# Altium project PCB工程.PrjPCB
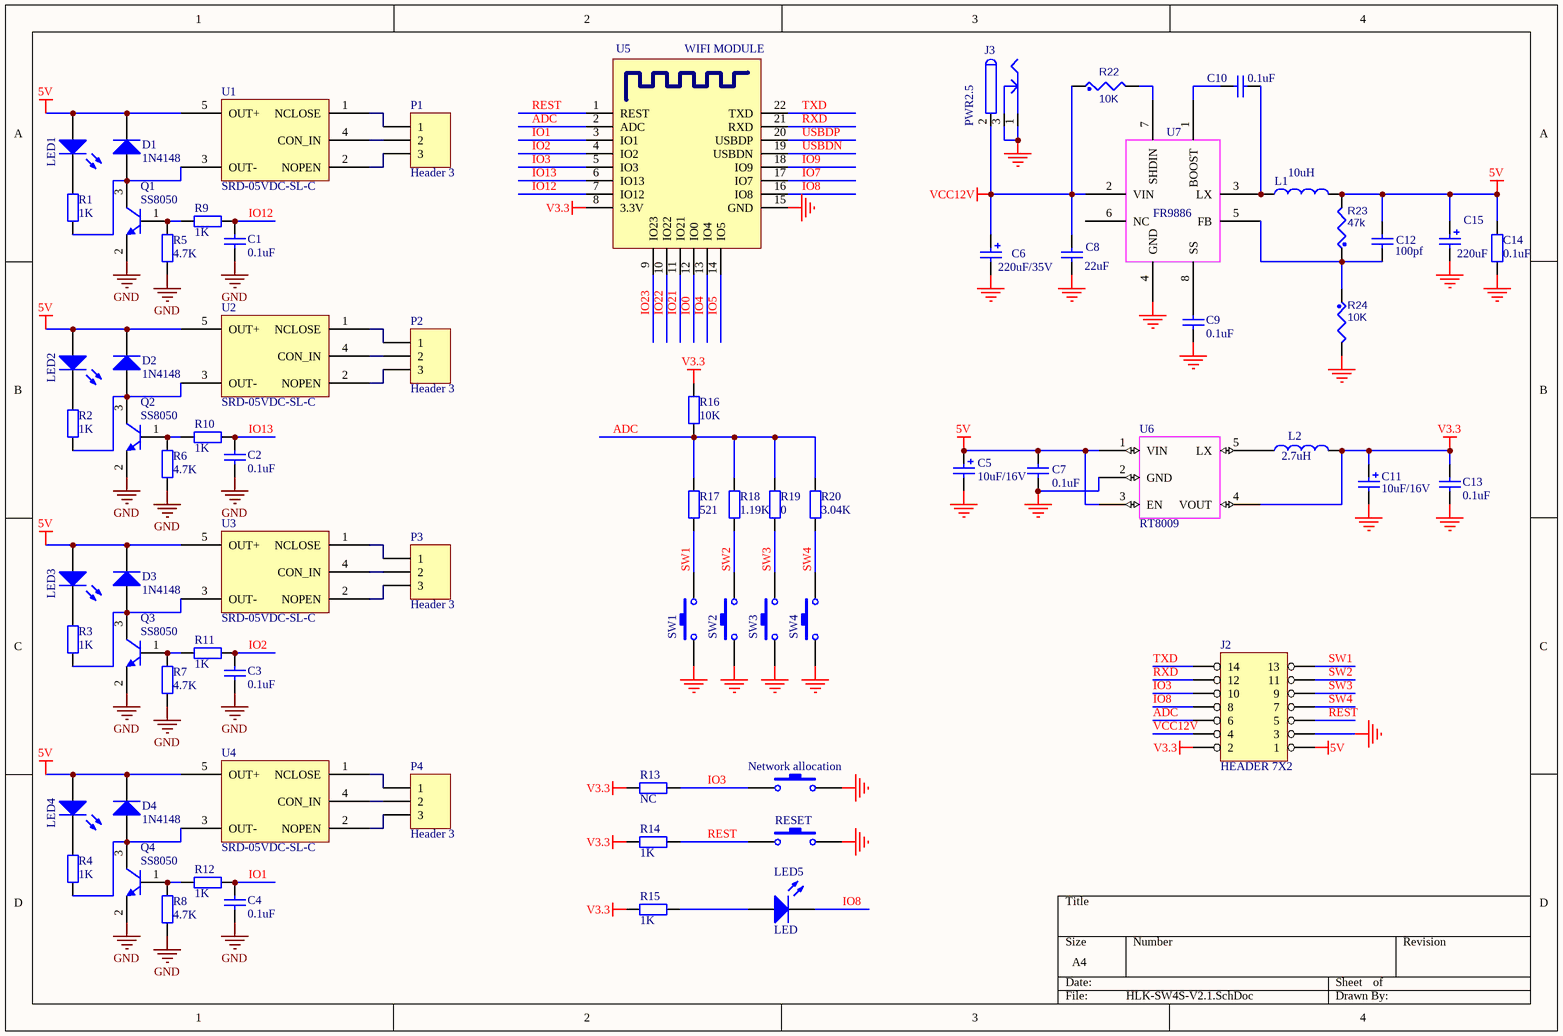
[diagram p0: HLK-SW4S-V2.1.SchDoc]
1 sheet, 72 parts. Net scope: global (net labels, ports and power ports of the same name join across sheets).
Board file: HLK-SW4S-V2.1.PcbDoc

## Sheet HLK-SW4S-V2.1.SchDoc
size A4

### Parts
C1  0.1uF  [0603L]
C2  0.1uF  [0603L]
C3  0.1uF  [0603L]
C4  0.1uF  [0603L]
C5  10uF/16V  [0805S]
C6  220uF/35V  [CAP_SMT_6.3]
C7  0.1uF  [0603L]
C8  22uF  [0805S]
C9  0.1uF  [0603L]
C10  0.1uF  [0603L]
C11  10uF/16V  [0805S]
C12  100pf  [0603L]
C13  0.1uF  [0603L]
C14  0.1uF  [0805S]
C15  220uF  [CAP_SMT_6.3]
D1  1N4148  [LED1]
D2  1N4148  [LED1]
D3  1N4148  [LED1]
D4  1N4148  [LED1]
J2  HEADER 7X2  [HDR2X7]
J3  PWR2.5  [POWER_STK1]
L1  10uH  [L7x7]
L2  2.7uH  [L322520]
LED1  LED  [0603LED]  (value not drawn)
LED2  LED  [0603LED]  (value not drawn)
LED3  LED  [0603LED]  (value not drawn)
LED4  LED  [0603LED]  (value not drawn)
LED5  LED  [0603LED]
Network_allocation  SW-PB  [KEY]  (value not drawn)
P1  Header 3  [5MMX3]
P2  Header 3  [5MMX3]
P3  Header 3  [5MMX3]
P4  Header 3  [5MMX3]
Q1  SS8050  [SOT-23]
Q2  SS8050  [SOT-23]
Q3  SS8050  [SOT-23]
Q4  SS8050  [SOT-23]
R1  1K  [0603L]
R2  1K  [0603L]
R3  1K  [0603L]
R4  1K  [0603L]
R5  4.7K  [0603L]
R6  4.7K  [0603L]
R7  4.7K  [0603L]
R8  4.7K  [0603L]
R9  1K  [0603L]
R10  1K  [0603L]
R11  1K  [0603L]
R12  1K  [0603L]
R13  NC  [0603L]
R14  1K  [0603L]
R15  1K  [0603L]
R16  10K  [0603L]
R17  521  [0603L]
R18  1.19K  [0603L]
R19  0  [0603L]
R20  3.04K  [0603L]
R22  10K  [0603L]
R23  47k  [0603L]
R24  10K  [0603L]
RESET  SW-PB  [KEY]  (value not drawn)
SW1  SW-PB  [KEY]  (value not drawn)
SW2  SW-PB  [KEY]  (value not drawn)
SW3  SW-PB  [KEY]  (value not drawn)
SW4  SW-PB  [KEY]  (value not drawn)
U1  SRD-05VDC-SL-C  [SRD-05VDC-SL-C]
U2  SRD-05VDC-SL-C  [SRD-05VDC-SL-C]
U3  SRD-05VDC-SL-C  [SRD-05VDC-SL-C]
U4  SRD-05VDC-SL-C  [SRD-05VDC-SL-C]
U5  WIFI MODULE  [MOD1]
U6  RT8009  [SOT-25]
U7  FR9886  [SOP8]

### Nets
5V: C5.1 C7.2 C12.1 C14.2 C15.1 D1.2(K) D2.2(K) D3.2(K) D4.2(K) J2.1 L1.2 LED1.1(A) LED2.1(A) LED3.1(A) LED4.1(A) R23.2 U1.5(OUT+) U2.5(OUT+) U3.5(OUT+) U4.5(OUT+) U6.1(VIN) U6.3(EN)
GND: C1.1 C2.1 C3.1 C4.1 C5.2 C6.2 C7.1 C8.2 C9.1 C11.2 C13.1 C14.1 C15.2 J2.3 J3.1 J3.3 Network_allocation.2 Q1.2(E) Q2.2(E) Q3.2(E) Q4.2(E) R5.1 R6.1 R7.1 R8.1 R24.2 RESET.1 SW1.1 SW2.1 SW3.1 SW4.1 U5.15(GND) U6.2(GND) U7.4(GND)
V3.3: C11.1 C13.2 J2.2 L2.2 R13.1 R14.1 R15.2 R16.2 U5.8(3.3V) U6.4(VOUT)
VCC12V: C6.1 C8.1 J2.4 J3.2 R22.1 U7.2(VIN)
ADC: J2.6 R16.1 R17.2 R18.2 R19.2 R20.2 U5.2(ADC)
IO0: U5.12(IO0)
IO1: C4.2 R12.2 U5.3(IO1)
IO2: C3.2 R11.2 U5.4(IO2)
IO3: J2.10 Network_allocation.1 R13.2 U5.5(IO3)
IO4: U5.13(IO4)
IO5: U5.14(IO5)
IO7: U5.17(IO7)
IO8: J2.8 LED5.2(K) U5.16(IO8)
IO9: U5.18(IO9)
IO12: C1.2 R9.2 U5.7(IO12)
IO13: C2.2 R10.1 U5.6(IO13)
IO21: U5.11(IO21)
IO22: U5.10(IO22)
IO23: U5.9(IO23)
REST: J2.5 R14.2 RESET.2 U5.1(REST)
RXD: J2.12 U5.21(RXD)
SW1: J2.13 R17.1 SW1.2
SW2: J2.11 R18.1 SW2.2
SW3: J2.9 R19.1 SW3.2
SW4: J2.7 R20.1 SW4.2
TXD: J2.14 U5.22(TXD)
USBDN: U5.19(USBDN)
USBDP: U5.20(USBDP)
NetC9_2: C9.2 U7.8(SS)
NetC10_1: C10.1 L1.1 U7.3(LX)
NetC10_2: C10.2 U7.1(BOOST)
NetC12_2: C12.2 R23.1 R24.1 U7.5(FB)
NetD1_1: D1.1(A) Q1.3(C) R1.1 U1.3(OUT-)
NetD2_1: D2.1(A) Q2.3(C) R2.1 U2.3(OUT-)
NetD3_1: D3.1(A) Q3.3(C) R3.1 U3.3(OUT-)
NetD4_1: D4.1(A) Q4.3(C) R4.1 U4.3(OUT-)
NetL2_1: L2.1 U6.5(LX)
NetLED1_2: LED1.2(K) R1.2
NetLED2_2: LED2.2(K) R2.2
NetLED3_2: LED3.2(K) R3.2
NetLED4_2: LED4.2(K) R4.2
NetLED5_1: LED5.1(A) R15.1
NetP1_1: P1.1 U1.1(NCLOSE)
NetP1_2: P1.2 U1.4(CON_IN)
NetP1_3: P1.3 U1.2(NOPEN)
NetP2_1: P2.1 U2.1(NCLOSE)
NetP2_2: P2.2 U2.4(CON_IN)
NetP2_3: P2.3 U2.2(NOPEN)
NetP3_1: P3.1 U3.1(NCLOSE)
NetP3_2: P3.2 U3.4(CON_IN)
NetP3_3: P3.3 U3.2(NOPEN)
NetP4_1: P4.1 U4.1(NCLOSE)
NetP4_2: P4.2 U4.4(CON_IN)
NetP4_3: P4.3 U4.2(NOPEN)
NetQ1_1: Q1.1(B) R5.2 R9.1
NetQ2_1: Q2.1(B) R6.2 R10.2
NetQ3_1: Q3.1(B) R7.2 R11.1
NetQ4_1: Q4.1(B) R8.2 R12.1
NetR22_2: R22.2 U7.7(SHDIN)

Not connected (* = marked no-connect by the designer): U7 6(NC)

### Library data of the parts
C1-C4 C7-C10 C13 = Cap: Capacitor; Manufacturer: Generic Components; Class: Passive; Value: 100pF
C5 C6 C11 C15 = Cap Pol3: Polarized Capacitor (Surface Mount); Manufacturer: Generic Components; Class: Passive; Value: 10uF
C12 = Cap: Capacitor; Manufacturer: Generic Components; Class: Passive
C14 R1-R15 R17-R20 = Res2: Resistor; Value: 10K
D1-D4 = Diode: Default Diode
J3 = PWR2.5: Low Voltage Power Supply Connector
L1 L2 = INDUCTOR1
LED1-LED5 = LED0: Typical INFRARED GaAs LED
Network_allocation RESET SW1-SW4 = SW-PB: Switch
P1-P4 = Header 3: Header, 3-Pin
Q1-Q4 = 2N3904: PNP General Purpose Amplifier
R16 = Res2: Resistor
R22-R24 = 0603_10 K_1%_1/10W: RES, SO, 0603, 10K, 1%, 1/10W; Ordering: CRCW060310K0FKEA; MFG: Vishay/Dale; Right: 20; Bottom: 30
U1-U4 = SRD
U5 = MOD1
